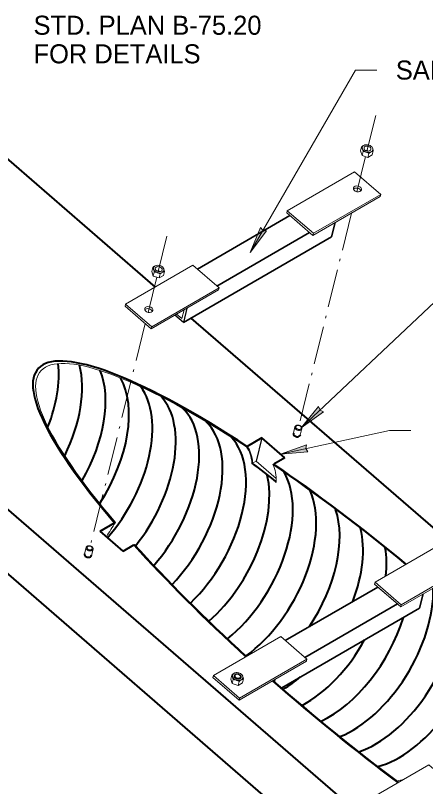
# Model space of a CAD drawing. Extents: x 99860 to 103153, y 99998 to 102077.
# Drawn here: x 101841 to 102185, y 100418 to 101065 of the extents above; entities that cross this region are included whole.
import ezdxf

# ---------------------------------------------------------------- set-up
doc = ezdxf.new("R2010")
doc.units = 0
doc.header["$LTSCALE"] = 6.4
doc.linetypes.add('DOT_DASHED', pattern=[7.7, 5, -1.2, 0.3, -1.2])
for name, color, linetype, lineweight in [('1', 7, 'Continuous', 13), ('15', 7, 'Continuous', 13), ('20', 7, 'Continuous', 13), ('30', 7, 'Continuous', 40), ('9', 7, 'Continuous', 13)]:
    doc.layers.add(name, color=color, linetype=linetype, lineweight=lineweight)

msp = doc.modelspace()

# ---------------------------------------------------------------- hatches: boundary and pattern name
at = {"layer": '15'}
for points in [[(102037.969, 100866.02), (102046.727, 100887.063), (102048.761, 100884.677), (102051.843, 100884.104)], [(102081.009, 100718.734), (102099.655, 100732.238), (102096.837, 100733.682), (102095.556, 100736.579)], [(102063.63, 100696.624), (102086.569, 100698.589), (102084.897, 100701.279), (102085.293, 100704.421)]]:
    msp.add_hatch(color=256, dxfattribs=at).paths.add_polyline_path(points)

# ---------------------------------------------------------------- linework, layer by layer
at = {"layer": '1', "lineweight": 40}
for p, q in [((101757.422, 101010.798), (101958.147, 100836.965)), ((101553.775, 100893.223), (102304.358, 100243.197)), ((102259.104, 100228.525), (101542.799, 100848.864)), ((101988.262, 100810.884), (102508.005, 100360.773)), ((102047.901, 100710.246), (102035.616, 100703.154)), ((102067.104, 100693.615), (102047.901, 100710.246)), ((102067.109, 100693.606), (102057.884, 100688.28)), ((101912.136, 100631.862), (101924.259, 100638.862)), ((101931.348, 100615.224), (101912.136, 100631.862)), ((101931.348, 100615.224), (101940.404, 100620.453))]:
    msp.add_line(p, q, dxfattribs=at)
at = {"layer": '1'}
for p, q in [((102069.165, 100901.061), (102125.734, 100933.721)), ((102147.685, 100914.71), (102125.734, 100933.721)), ((102090.688, 100880.317), (102147.257, 100912.977)), ((102091.117, 100882.05), (102147.685, 100914.71)), ((102147.257, 100912.977), (102147.685, 100914.71)), ((102069.165, 100901.061), (102068.736, 100899.328)), ((102068.736, 100899.328), (102090.688, 100880.317)), ((102091.117, 100882.05), (102069.165, 100901.061)), ((102090.688, 100880.317), (102091.117, 100882.05)), ((102011.492, 100834.593), (101954.924, 100801.933)), ((102011.921, 100836.326), (101955.352, 100803.666)), ((102011.492, 100834.593), (102011.921, 100836.326)), ((101955.352, 100803.666), (101933.401, 100822.677)), ((101980.718, 100810.489), (101976.328, 100814.291)), ((101982.548, 100817.882), (101980.718, 100810.489)), ((101954.924, 100801.933), (101955.352, 100803.666)), ((102034.925, 100702.755), (102035.616, 100703.154)), ((102039.523, 100688.857), (102040.115, 100689.198)), ((102043.069, 100690.864), (102040.115, 100689.198)), ((102043.069, 100690.864), (102059.98, 100676.219)), ((102057.884, 100688.28), (102057.23, 100687.902)), ((101924.259, 100638.862), (101924.95, 100639.261)), ((101941.058, 100620.831), (101940.404, 100620.453)), ((102142.973, 100589.19), (102199.542, 100621.849)), ((102164.496, 100568.446), (102221.065, 100601.106)), ((102164.925, 100570.179), (102221.494, 100602.839)), ((102142.973, 100589.19), (102142.544, 100587.457)), ((102142.544, 100587.457), (102164.496, 100568.446)), ((102164.925, 100570.179), (102142.973, 100589.19)), ((102145.288, 100585.08), (102161.752, 100570.822)), ((102164.496, 100568.446), (102164.925, 100570.179)), ((102063.778, 100543.466), (102007.21, 100510.806)), ((102085.73, 100524.455), (102063.778, 100543.466)), ((102085.301, 100522.723), (102028.733, 100490.063)), ((102007.21, 100510.806), (102006.781, 100509.074)), ((102028.733, 100490.063), (102006.781, 100509.074)), ((102029.161, 100491.796), (102007.21, 100510.806)), ((102028.733, 100490.063), (102057.069, 100506.423)), ((102028.733, 100490.063), (102029.161, 100491.796))]:
    msp.add_line(p, q, dxfattribs=at)
at = {"layer": '1', "lineweight": 35}
for p, q in [((102071.48, 100896.952), (101993.742, 100852.069)), ((102087.944, 100882.693), (102010.206, 100837.811)), ((102145.288, 100585.08), (102067.551, 100540.199)), ((102183.236, 100579.266), (102180.264, 100567.252)), ((102180.264, 100567.252), (102064.597, 100500.471)), ((102161.752, 100570.822), (102084.015, 100525.941)), ((102058.786, 100507.414), (102058.408, 100505.886))]:
    msp.add_line(p, q, dxfattribs=at)
at = {"layer": '1', "lineweight": 25}
for p, q in [((101984.977, 100819.285), (101982.005, 100807.271)), ((101982.005, 100807.271), (101974.87, 100813.45)), ((102047.901, 100710.246), (102043.069, 100690.864))]:
    msp.add_line(p, q, dxfattribs=at)
at = {"layer": '1', "lineweight": 35}
msp.add_lwpolyline([(102109.428, 100891.137), (102106.456, 100879.123), (101982.005, 100807.271)], dxfattribs=at)
at = {"layer": '1'}
for points in [[(102011.921, 100836.326), (101989.969, 100855.337), (101933.401, 100822.677)], [(101933.401, 100822.677), (101932.972, 100820.944), (101954.924, 100801.933)], [(102085.301, 100522.723), (102085.73, 100524.455), (102029.161, 100491.796)], [(102210.087, 100416.759), (102188.135, 100435.77), (102131.567, 100403.11)]]:
    msp.add_lwpolyline(points, dxfattribs=at)
for centre in [(102128.224, 100919.316), (101952.862, 100818.071)]:
    msp.add_ellipse(centre, major_axis=(-3.398, 0.841), ratio=0.700141, dxfattribs=at)
for centre, major_axis, ratio, start_param, end_param in [((102127.795, 100917.583), (3.398, -0.841), 0.700141, 0.3727897, 2.768803), ((101952.433, 100816.338), (3.398, -0.841), 0.700141, 0.3727897, 2.7688029), ((102135.042, 100536.619), (273.144, -229.43), 0.205372, 2.1111753, 4.0230218), ((101970.23, 100631.773), (61.991, 73.833), 0.422246, 5.8695175, 6.1871054), ((101970.23, 100631.773), (62.511, 74.453), 0.422246, 5.8669654, 6.1812326), ((102054.034, 100583.389), (275.824, -231.584), 0.205105, 1.7199266, 1.7910842), ((102054.034, 100583.389), (273.525, -229.654), 0.205105, 1.7197968, 1.7936362), ((102135.042, 100536.619), (273.144, -229.43), 0.205372, 1.6202443, 2.0261759), ((101990.638, 100619.991), (61.991, 73.833), 0.422246, 5.7956781, 6.102106), ((101970.23, 100631.773), (61.991, 73.833), 0.422246, 1.8157667, 1.9691344), ((102135.042, 100536.619), (273.144, -229.43), 0.205372, 4.1080212, 4.5139528), ((102135.042, 100536.619), (273.144, -229.43), 0.205372, 4.5997048, 4.9834755), ((102182.971, 100508.947), (-48, -83.138), 0.57735, 0.4620183, 0.5530209)]:
    msp.add_ellipse(centre, major_axis=major_axis, ratio=ratio, start_param=start_param, end_param=end_param, dxfattribs=at)
at = {"layer": '1', "lineweight": 40}
for centre, major_axis, ratio, start_param, end_param in [((102135.042, 100536.619), (275.44, -231.358), 0.205372, 2.1053025, 4.0288947), ((102077.247, 100713.409), (2.912, -0.721), 0.700141, 3.1416566, 4.8839278), ((102077.247, 100713.409), (2.912, -0.721), 0.700141, 4.8839277, 6.4278616), ((102135.042, 100536.619), (275.44, -231.358), 0.205372, 1.6192062, 2.0213016), ((102135.042, 100536.619), (275.44, -231.358), 0.205372, 4.1128955, 4.5149909), ((101901.884, 100612.163), (2.912, -0.721), 0.700141, 3.0998614, 4.8839277), ((101901.884, 100612.163), (2.912, -0.721), 0.700141, 4.8839277, 6.4074078), ((102135.042, 100536.619), (275.44, -231.358), 0.205372, 4.6000232, 4.9804768)]:
    msp.add_ellipse(centre, major_axis=major_axis, ratio=ratio, start_param=start_param, end_param=end_param, dxfattribs=at)
at = {"layer": '15'}
for p, q in [((102037.969, 100866.02), (102126.382, 101019.156)), ((102126.382, 101019.156), (102144.36, 101019.156)), ((102063.63, 100696.624), (102154.98, 100716.619)), ((102154.98, 100716.619), (102172.959, 100716.619))]:
    msp.add_line(p, q, dxfattribs=at)
at = {"layer": '15', "linetype": 'DOT_DASHED'}
for p, q in [((102143.462, 100980.865), (102136.112, 100951.178)), ((102134.957, 100946.502), (102127.638, 100916.937)), ((102123.219, 100899.099), (102078.651, 100719.071)), ((101968.099, 100879.62), (101960.749, 100849.932)), ((101959.592, 100845.258), (101952.271, 100815.692)), ((101949.935, 100806.254), (101903.281, 100617.821))]:
    msp.add_line(p, q, dxfattribs=at)
at = {"layer": '15'}
for points in [[(102037.969, 100866.02), (102046.727, 100887.063), (102048.761, 100884.677), (102051.843, 100884.104)], [(102081.009, 100718.734), (102099.655, 100732.238), (102096.837, 100733.682), (102095.556, 100736.579)], [(102063.63, 100696.624), (102086.569, 100698.589), (102084.897, 100701.279), (102085.293, 100704.421)]]:
    msp.add_lwpolyline(points, close=True, dxfattribs=at)
msp.add_lwpolyline([(102081.009, 100718.734), (102193.034, 100824.535), (102211.013, 100824.535)], dxfattribs=at)
at = {"layer": '30'}
for centre, start_param, end_param in [((101809.455, 100724.597), 1.8336274, 2.4727179), ((101829.114, 100713.247), 1.6865333, 2.6175266), ((101848.773, 100701.897), 1.5736342, 2.727204), ((101868.431, 100690.547), 1.4810912, 2.8184942), ((101888.09, 100679.197), 1.2472569, 2.896434), ((101907.749, 100667.847), 1.3130925, 2.96082), ((101927.408, 100656.497), 1.2396164, 3.0042015), ((101947.066, 100645.147), 1.1700917, 3.0076365), ((101966.725, 100633.797), 1.1036554, 2.9643206), ((101986.384, 100622.447), 1.0396751, 2.5932624), ((102006.042, 100611.097), 0.9776669, 2.8242576), ((102025.701, 100599.747), 0.9172483, 2.7497487), ((102045.36, 100588.397), 1.4641539, 2.675681), ((102065.019, 100577.047), 1.8455332, 2.6024098), ((102084.677, 100565.697), 2.2261506, 2.5315064), ((102123.995, 100542.997), 0.6296376, 2.3825459), ((102143.653, 100531.647), 0.573632, 2.3143778), ((102104.336, 100554.347), 0.6859299, 1.950535), ((102163.312, 100520.297), 0.5177897, 2.2422495), ((102084.677, 100565.697), 0.7426558, 1.6026539), ((102065.019, 100577.047), 0.7999841, 1.0147001)]:
    msp.add_ellipse(centre, major_axis=(-48, -83.138), ratio=0.57735, start_param=start_param, end_param=end_param, dxfattribs=at)
at = {"layer": '9'}
for p, q in [((102131.623, 100954.551), (102130.791, 100951.191)), ((102132.041, 100947.457), (102130.791, 100951.191)), ((102132.873, 100950.817), (102132.041, 100947.457)), ((102137.796, 100949.205), (102136.964, 100945.845)), ((102136.964, 100945.845), (102132.041, 100947.457)), ((101956.262, 100853.306), (101955.43, 100849.946)), ((101955.43, 100849.946), (101956.68, 100846.212)), ((101957.511, 100849.573), (101956.68, 100846.212)), ((101956.68, 100846.212), (101961.603, 100844.6)), ((101959.926, 100849.083), (101960.158, 100849.007)), ((101962.435, 100847.961), (101961.603, 100844.6)), ((101961.603, 100844.6), (101965.277, 100846.721)), ((101966.108, 100850.081), (101965.277, 100846.721)), ((102075.663, 100719.5), (102074.334, 100714.129)), ((102080.159, 100712.688), (102081.488, 100718.062)), ((101900.302, 100618.257), (101898.972, 100612.883)), ((101904.796, 100611.443), (101906.125, 100616.814)), ((102022.578, 100511.173), (102021.747, 100507.813)), ((102021.747, 100507.813), (102022.996, 100504.079)), ((102023.249, 100509.652), (102023.295, 100509.516)), ((102032.425, 100507.948), (102031.593, 100504.588)), ((102023.828, 100507.44), (102022.996, 100504.079)), ((102022.996, 100504.079), (102027.92, 100502.467)), ((102026.242, 100506.95), (102026.475, 100506.874)), ((102028.751, 100505.828), (102027.92, 100502.467)), ((102027.92, 100502.467), (102031.593, 100504.588)), ((102030.578, 100507.12), (102030.735, 100507.211))]:
    msp.add_line(p, q, dxfattribs=at)
msp.add_lwpolyline([(102141.47, 100951.327), (102140.638, 100947.966), (102136.964, 100945.845)], dxfattribs=at)
for centre, major_axis, start_param, end_param in [((102136.616, 100953.217), (4.368, -1.081), 2.5125792, 4.5937904), ((102136.616, 100953.217), (4.368, -1.081), 1.4862714, 2.5125792), ((102136.616, 100953.217), (4.368, -1.081), 0.4454258, 1.4444918), ((102135.716, 100949.578), (2.912, -0.721), 1.1024736, 2.0391191), ((102136.616, 100953.217), (4.368, -1.081), 4.6202037, 5.6294447), ((102136.616, 100953.217), (4.368, -1.081), 5.678899, 6.6741277), ((101961.254, 100851.971), (4.368, -1.081), 2.5125792, 3.5388869), ((101961.254, 100851.971), (4.368, -1.081), 3.5806665, 4.5797326), ((101961.254, 100851.971), (4.368, -1.081), 0.431368, 2.5125792), ((101961.254, 100851.971), (4.368, -1.081), 5.678899, 6.68814), ((101960.353, 100848.332), (2.912, -0.721), 1.1024735, 2.0391191), ((101961.254, 100851.971), (4.368, -1.081), 4.634216, 5.6294447), ((102027.57, 100509.838), (4.368, -1.081), 2.5125792, 3.5388869), ((102027.57, 100509.838), (4.368, -1.081), 3.5806665, 4.5797326), ((102027.57, 100509.838), (-2.912, 0.721), 5.6541718, 6.7144408), ((102027.57, 100509.838), (2.912, -0.721), 2.1677633, 5.9990162), ((102027.57, 100509.838), (4.368, -1.081), 0.431368, 2.5125792), ((102027.57, 100509.838), (4.368, -1.081), 5.678899, 6.68814), ((102027.57, 100509.838), (4.368, -1.081), 4.634216, 5.6294447)]:
    msp.add_ellipse(centre, major_axis=major_axis, ratio=0.700141, start_param=start_param, end_param=end_param, dxfattribs=at)
for centre, major_axis in [((102136.616, 100953.217), (-2.912, 0.721)), ((101961.254, 100851.971), (-2.912, 0.721)), ((102078.651, 100719.071), (2.213, -0.548)), ((101903.281, 100617.821), (2.213, -0.548)), ((102027.638, 100510.125), (2.213, -0.548))]:
    msp.add_ellipse(centre, major_axis=major_axis, ratio=0.700141, dxfattribs=at)
for points in [[(102133.529, 100955.89), (102133.372, 100955.799), (102133.213, 100955.702), (102133.053, 100955.598), (102132.581, 100955.293), (102132.1, 100954.934), (102131.623, 100954.551)], [(102132.873, 100950.817), (102132.701, 100951.643), (102132.502, 100952.434), (102132.273, 100953.091), (102132.073, 100953.664), (102131.85, 100954.144), (102131.623, 100954.551)], [(102135.348, 100950.308), (102135.309, 100950.32), (102135.271, 100950.332), (102135.232, 100950.344), (102134.455, 100950.585), (102133.655, 100950.731), (102132.873, 100950.817)], [(102137.796, 100949.205), (102137.057, 100949.625), (102136.271, 100950.001), (102135.461, 100950.271)], [(102139.624, 100950.499), (102139.492, 100950.421), (102139.36, 100950.339), (102139.227, 100950.253), (102138.755, 100949.948), (102138.273, 100949.589), (102137.796, 100949.205)], [(102141.47, 100951.327), (102141.338, 100951.285), (102141.204, 100951.239), (102141.069, 100951.189), (102140.658, 100951.038), (102140.226, 100950.841), (102139.781, 100950.59)], [(102140.943, 100953.383), (102140.948, 100953.369), (102140.952, 100953.355), (102140.957, 100953.341), (102141.15, 100952.741), (102141.32, 100952.048), (102141.47, 100951.327)], [(101956.262, 100853.306), (101956.413, 100853.428), (101956.565, 100853.547), (101956.717, 100853.663), (101957.204, 100854.035), (101957.694, 100854.372), (101958.167, 100854.645)], [(101956.262, 100853.306), (101956.497, 100852.885), (101956.728, 100852.385), (101956.933, 100851.785)], [(101956.978, 100851.649), (101956.985, 100851.629), (101956.992, 100851.608), (101956.998, 100851.587), (101957.192, 100850.987), (101957.361, 100850.294), (101957.511, 100849.573)], [(101966.108, 100850.081), (101965.951, 100850.837), (101965.772, 100851.563), (101965.567, 100852.183)], [(101957.511, 100849.573), (101958.312, 100849.484), (101959.132, 100849.333), (101959.926, 100849.083)], [(101960.158, 100849.007), (101960.176, 100849), (101960.194, 100848.994), (101960.212, 100848.988), (101960.983, 100848.722), (101961.73, 100848.361), (101962.435, 100847.961)], [(101962.435, 100847.961), (101962.586, 100848.083), (101962.738, 100848.202), (101962.89, 100848.318), (101963.35, 100848.669), (101963.813, 100848.989), (101964.261, 100849.253)], [(101964.418, 100849.344), (101964.549, 100849.418), (101964.678, 100849.487), (101964.806, 100849.551), (101965.259, 100849.78), (101965.694, 100849.95), (101966.108, 100850.081)], [(102078.304, 100716.69), (102078.633, 100716.628), (102078.972, 100716.605), (102079.293, 100716.624), (102079.614, 100716.643), (102079.926, 100716.704), (102080.202, 100716.801), (102080.478, 100716.899), (102080.727, 100717.036), (102080.927, 100717.202), (102081.128, 100717.367), (102081.286, 100717.566), (102081.388, 100717.78), (102081.49, 100717.995), (102081.539, 100718.232), (102081.531, 100718.472), (102081.523, 100718.712), (102081.458, 100718.961), (102081.341, 100719.198), (102081.224, 100719.436), (102081.052, 100719.669), (102080.84, 100719.878), (102080.627, 100720.086), (102080.367, 100720.277), (102080.083, 100720.433), (102079.798, 100720.59), (102079.48, 100720.716), (102079.156, 100720.803), (102078.832, 100720.889), (102078.491, 100720.937), (102078.164, 100720.944), (102077.836, 100720.951), (102077.512, 100720.916), (102077.218, 100720.842), (102076.924, 100720.768), (102076.653, 100720.653), (102076.426, 100720.507), (102076.199, 100720.361), (102076.01, 100720.18), (102075.875, 100719.978), (102075.741, 100719.776), (102075.657, 100719.548), (102075.63, 100719.314), (102075.603, 100719.079), (102075.632, 100718.831), (102075.716, 100718.589), (102075.8, 100718.348), (102075.94, 100718.107), (102076.125, 100717.887), (102076.31, 100717.666), (102076.545, 100717.46), (102076.81, 100717.285), (102077.076, 100717.11), (102077.379, 100716.962), (102077.695, 100716.852), (102077.892, 100716.783), (102078.097, 100716.729), (102078.304, 100716.69)], [(101906.163, 100617.304), (101906.183, 100617.064), (101906.147, 100616.824), (101906.057, 100616.606), (101905.967, 100616.388), (101905.821, 100616.184), (101905.631, 100616.013), (101905.441, 100615.841), (101905.201, 100615.696), (101904.932, 100615.591), (101904.663, 100615.485), (101904.357, 100615.416), (101904.039, 100615.388), (101903.722, 100615.361), (101903.384, 100615.374), (101903.054, 100615.428), (101902.723, 100615.482), (101902.392, 100615.577), (101902.086, 100615.705), (101901.78, 100615.834), (101901.492, 100616), (101901.245, 100616.189), (101900.999, 100616.378), (101900.786, 100616.596), (101900.627, 100616.824), (101900.467, 100617.053), (101900.355, 100617.298), (101900.299, 100617.54), (101900.244, 100617.782), (101900.245, 100618.027), (101900.301, 100618.255), (101900.357, 100618.483), (101900.47, 100618.7), (101900.631, 100618.889), (101900.792, 100619.078), (101901.004, 100619.243), (101901.252, 100619.37), (101901.499, 100619.498), (101901.788, 100619.592), (101902.094, 100619.645), (101902.4, 100619.698), (101902.732, 100619.71), (101903.062, 100619.682), (101903.393, 100619.653), (101903.73, 100619.583), (101904.048, 100619.477), (101904.365, 100619.37), (101904.671, 100619.225), (101904.939, 100619.053), (101905.208, 100618.88), (101905.446, 100618.676), (101905.636, 100618.457), (101905.825, 100618.239), (101905.971, 100617.999), (101906.06, 100617.758), (101906.115, 100617.608), (101906.15, 100617.455), (101906.163, 100617.304)], [(102022.578, 100511.173), (102022.73, 100511.295), (102022.882, 100511.414), (102023.034, 100511.53), (102023.52, 100511.902), (102024.01, 100512.239), (102024.483, 100512.512)], [(102022.578, 100511.173), (102022.814, 100510.752), (102023.044, 100510.252), (102023.249, 100509.652)], [(102023.295, 100509.516), (102023.301, 100509.496), (102023.308, 100509.475), (102023.315, 100509.454), (102023.508, 100508.854), (102023.678, 100508.161), (102023.828, 100507.44)], [(102024.483, 100512.512), (102024.641, 100512.602), (102024.796, 100512.687), (102024.95, 100512.764), (102025.403, 100512.993), (102025.837, 100513.163), (102026.252, 100513.294)], [(102030.52, 100509.608), (102030.54, 100509.367), (102030.504, 100509.128), (102030.414, 100508.909), (102030.324, 100508.691), (102030.178, 100508.488), (102029.988, 100508.316), (102029.798, 100508.144), (102029.558, 100508), (102029.289, 100507.894), (102029.02, 100507.789), (102028.714, 100507.719), (102028.396, 100507.692), (102028.079, 100507.664), (102027.741, 100507.678), (102027.411, 100507.731), (102027.08, 100507.785), (102026.749, 100507.88), (102026.443, 100508.009), (102026.137, 100508.137), (102025.849, 100508.303), (102025.602, 100508.492), (102025.356, 100508.681), (102025.143, 100508.899), (102024.984, 100509.128), (102024.824, 100509.356), (102024.712, 100509.601), (102024.656, 100509.843), (102024.601, 100510.085), (102024.602, 100510.33), (102024.658, 100510.558), (102024.714, 100510.786), (102024.827, 100511.004), (102024.988, 100511.192), (102025.149, 100511.381), (102025.361, 100511.546), (102025.609, 100511.674), (102025.856, 100511.802), (102026.145, 100511.896), (102026.451, 100511.948), (102026.757, 100512.001), (102027.089, 100512.014), (102027.419, 100511.985), (102027.75, 100511.957), (102028.087, 100511.886), (102028.405, 100511.78), (102028.722, 100511.674), (102029.028, 100511.528), (102029.296, 100511.356), (102029.565, 100511.184), (102029.803, 100510.98), (102029.993, 100510.761), (102030.182, 100510.542), (102030.328, 100510.302), (102030.417, 100510.062), (102030.472, 100509.911), (102030.507, 100509.758), (102030.52, 100509.608)], [(102031.175, 100511.681), (102030.368, 100512.14), (102029.501, 100512.545), (102028.611, 100512.821), (102027.834, 100513.061), (102027.034, 100513.207), (102026.252, 100513.294)], [(102030.735, 100507.211), (102030.865, 100507.285), (102030.995, 100507.354), (102031.123, 100507.418), (102031.575, 100507.647), (102032.01, 100507.817), (102032.425, 100507.948)], [(102031.855, 100510.135), (102031.845, 100510.164), (102031.835, 100510.193), (102031.825, 100510.221), (102031.625, 100510.795), (102031.403, 100511.274), (102031.175, 100511.681)], [(102032.425, 100507.948), (102032.268, 100508.704), (102032.088, 100509.43), (102031.883, 100510.05)], [(102023.828, 100507.44), (102024.629, 100507.351), (102025.448, 100507.2), (102026.242, 100506.95)], [(102026.475, 100506.874), (102026.493, 100506.867), (102026.511, 100506.861), (102026.528, 100506.855), (102027.299, 100506.589), (102028.046, 100506.228), (102028.751, 100505.828)], [(102028.751, 100505.828), (102028.903, 100505.95), (102029.055, 100506.069), (102029.207, 100506.185), (102029.666, 100506.536), (102030.129, 100506.856), (102030.578, 100507.12)]]:
    msp.add_open_spline(points, degree=3, dxfattribs=at)

# ---------------------------------------------------------------- texts
at = {"layer": '20'}
for s, p in [('STD. PLAN B-75.20', (101856.132, 101048.78)), ('FOR DETAILS', (101856.132, 101024.78)), ('SAFETY BAR (TYP.)', (102160.36, 101011.156))]:
    msp.add_text(s, height=16, dxfattribs=at).set_placement(p)

doc.saveas('drawing.dxf')
